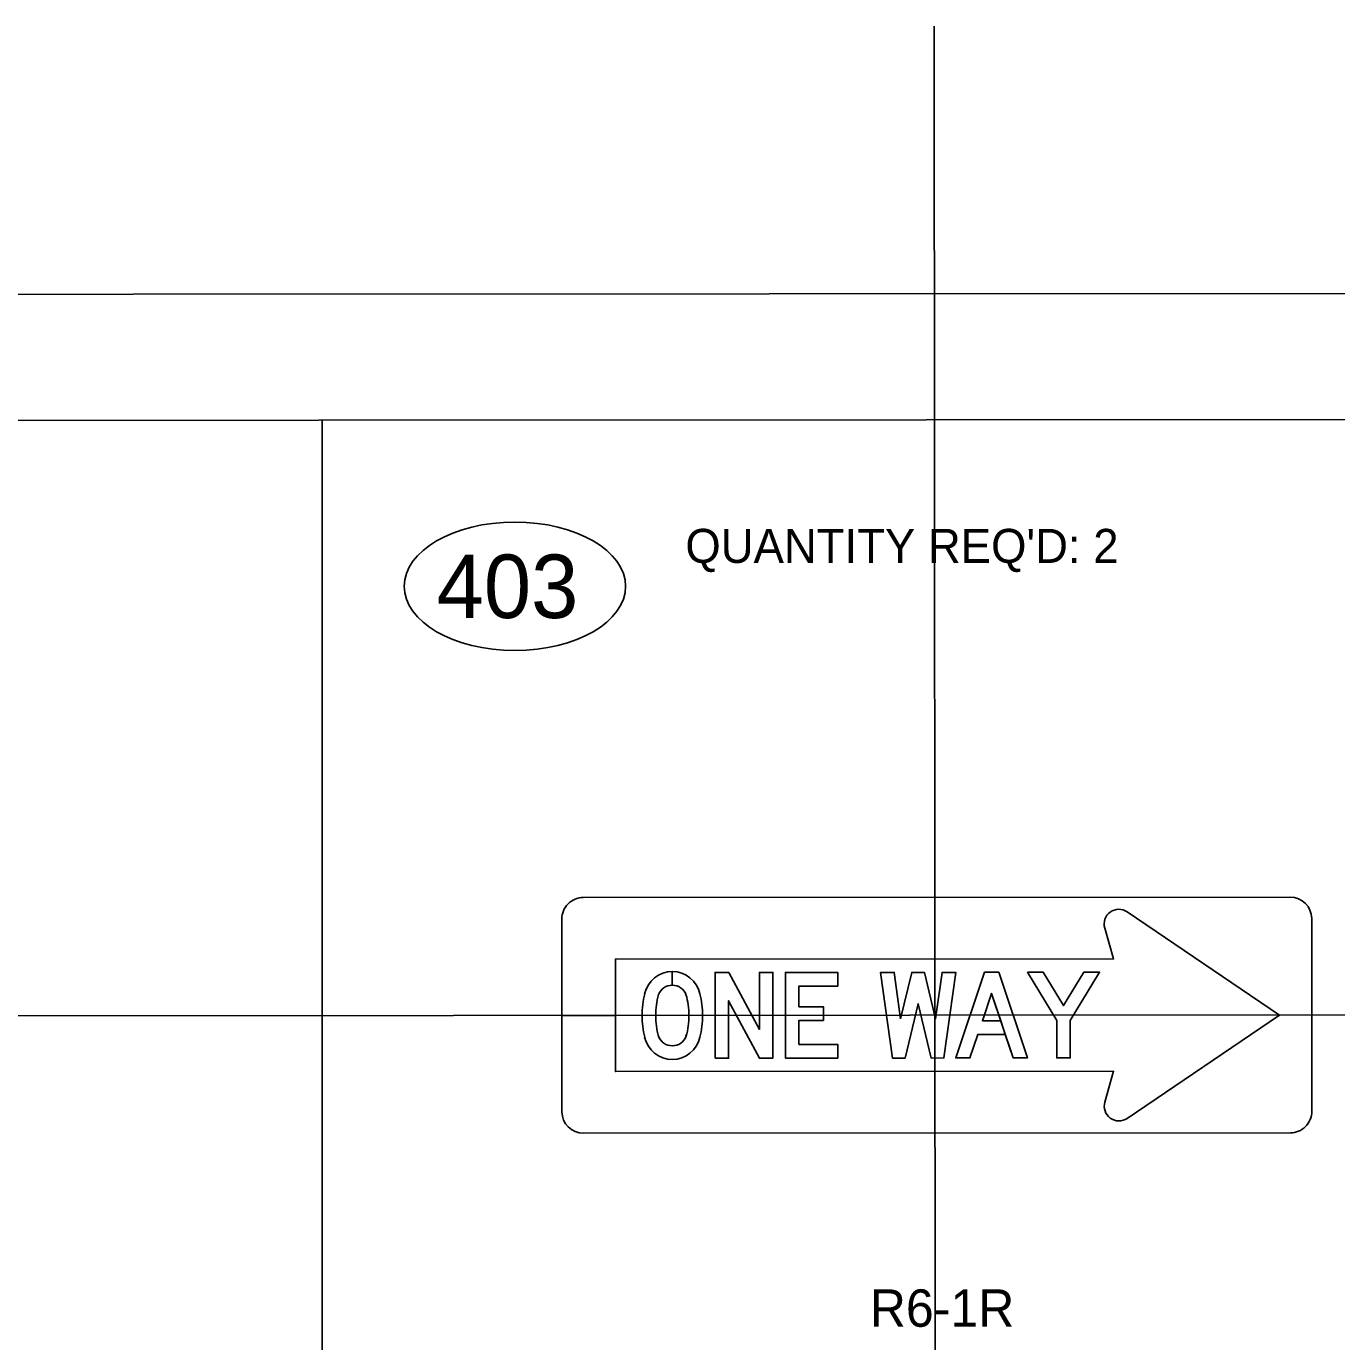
# Model space of a CAD drawing. Extents: x 1977705 to 1981198, y 827296 to 829291.
# Drawn here: x 1979879 to 1980110.2, y 828551.2 to 828783.3 of the extents above; entities that cross this region are included whole.
import ezdxf

# ---------------------------------------------------------------- set-up
doc = ezdxf.new("R2010")
doc.units = 0
for name, color, linetype in [('Level 3', 7, 'Continuous'), ('Level 34', 7, 'Continuous'), ('Level 43', 7, 'Continuous'), ('Level 7', 7, 'Continuous')]:
    doc.layers.add(name, color=color, linetype=linetype)

msp = doc.modelspace()

# ---------------------------------------------------------------- linework, layer by layer
at = {"layer": 'Level 3'}
msp.add_lwpolyline([(1981020.16, 828736.58), (1979336.66, 828735.68), (1979337.25, 827640.68), (1981020.75, 827641.58)], close=True, dxfattribs=at)
at = {"layer": 'Level 34'}
for p, q in [((1980039.8, 827664.08), (1980039.2, 828783.26)), ((1980814.89, 828609.21), (1979481.21, 828608.49))]:
    msp.add_line(p, q, dxfattribs=at)
at = {"layer": 'Level 43'}
for p, q in [((1979977.26, 828629.55), (1980102, 828629.61)), ((1980105.78, 828625.84), (1980105.8, 828591.82)), ((1979992.98, 828614.08), (1979992.97, 828616.51)), ((1979992.97, 828616.51), (1979992.98, 828614.08)), ((1979992.98, 828614.08), (1979992.97, 828616.51)), ((1979992.97, 828616.51), (1979992.98, 828614.08)), ((1979992.98, 828614.08), (1979992.98, 828614.08)), ((1979992.98, 828614.08), (1979992.98, 828614.08)), ((1980102.02, 828588.03), (1979977.28, 828587.97))]:
    msp.add_line(p, q, dxfattribs=at)
for points in [[(1980069.27, 828624.16), (1980070.82, 828618.73), (1979982.93, 828618.68), (1979982.94, 828608.76), (1979973.49, 828608.76), (1979973.48, 828625.77)], [(1980073.24, 828590.59), (1980100.12, 828608.82), (1980073.22, 828627.02)], [(1979973.5, 828591.75), (1979973.49, 828608.76), (1979982.94, 828608.76), (1979982.95, 828598.84), (1980070.83, 828598.89), (1980069.28, 828593.46)]]:
    msp.add_lwpolyline(points, dxfattribs=at)
for points in [[(1980000.52, 828601.21), (1980000.51, 828616.33), (1980002.93, 828616.33), (1980008.34, 828606.27), (1980008.34, 828616.33), (1980010.72, 828616.34), (1980010.73, 828601.22), (1980008.35, 828601.21), (1980002.9, 828611.33), (1980002.91, 828601.21)], [(1980000.52, 828601.21), (1980000.51, 828616.33), (1980002.93, 828616.33), (1980008.34, 828606.27), (1980008.34, 828616.33), (1980010.72, 828616.34), (1980010.73, 828601.22), (1980008.35, 828601.21), (1980002.9, 828611.33), (1980002.91, 828601.21)], [(1980000.52, 828601.21), (1980000.51, 828616.33), (1980002.93, 828616.33), (1980008.34, 828606.27), (1980008.34, 828616.33), (1980010.72, 828616.34), (1980010.73, 828601.22), (1980008.35, 828601.21), (1980002.9, 828611.33), (1980002.91, 828601.21)], [(1980022.16, 828613.92), (1980015.31, 828613.92), (1980015.31, 828610.29), (1980019.64, 828610.29), (1980019.64, 828607.87), (1980015.31, 828607.87), (1980015.31, 828603.64), (1980022.16, 828603.64), (1980022.16, 828601.22), (1980012.93, 828601.22), (1980012.92, 828616.34), (1980022.16, 828616.34)], [(1980022.16, 828613.92), (1980015.31, 828613.92), (1980015.31, 828610.29), (1980019.64, 828610.29), (1980019.64, 828607.87), (1980015.31, 828607.87), (1980015.31, 828603.64), (1980022.16, 828603.64), (1980022.16, 828601.22), (1980012.93, 828601.22), (1980012.92, 828616.34), (1980022.16, 828616.34)], [(1980022.16, 828613.92), (1980015.31, 828613.92), (1980015.31, 828610.29), (1980019.64, 828610.29), (1980019.64, 828607.87), (1980015.31, 828607.87), (1980015.31, 828603.64), (1980022.16, 828603.64), (1980022.16, 828601.22), (1980012.93, 828601.22), (1980012.92, 828616.34), (1980022.16, 828616.34)], [(1980033.25, 828608.17), (1980035.22, 828616.35), (1980037.46, 828616.35), (1980039.44, 828608.17), (1980040.56, 828616.35), (1980042.97, 828616.35), (1980040.89, 828601.24), (1980038.66, 828601.23), (1980036.34, 828610.82), (1980034.03, 828601.23), (1980031.81, 828601.23), (1980029.71, 828616.35), (1980032.12, 828616.35)], [(1980033.25, 828608.17), (1980035.22, 828616.35), (1980037.46, 828616.35), (1980039.44, 828608.17), (1980040.56, 828616.35), (1980042.97, 828616.35), (1980040.89, 828601.24), (1980038.66, 828601.23), (1980036.34, 828610.82), (1980034.03, 828601.23), (1980031.81, 828601.23), (1980029.71, 828616.35), (1980032.12, 828616.35)], [(1980033.25, 828608.17), (1980035.22, 828616.35), (1980037.46, 828616.35), (1980039.44, 828608.17), (1980040.56, 828616.35), (1980042.97, 828616.35), (1980040.89, 828601.24), (1980038.66, 828601.23), (1980036.34, 828610.82), (1980034.03, 828601.23), (1980031.81, 828601.23), (1980029.71, 828616.35), (1980032.12, 828616.35)], [(1980046.88, 828605.39), (1980045.49, 828601.24), (1980042.97, 828601.24), (1980048.03, 828616.36), (1980050.56, 828616.36), (1980055.63, 828601.24), (1980053.12, 828601.24), (1980051.72, 828605.4)], [(1980042.97, 828601.24), (1980048.03, 828616.36), (1980050.56, 828616.36), (1980055.63, 828601.24), (1980053.12, 828601.24), (1980049.3, 828612.62), (1980047.69, 828607.81), (1980050.91, 828607.81), (1980051.72, 828605.4), (1980046.88, 828605.39), (1980045.49, 828601.24)], [(1980042.97, 828601.24), (1980048.03, 828616.36), (1980050.56, 828616.36), (1980055.63, 828601.24), (1980053.12, 828601.24), (1980049.3, 828612.62), (1980047.69, 828607.81), (1980050.91, 828607.81), (1980051.72, 828605.4), (1980046.88, 828605.39), (1980045.49, 828601.24)], [(1980055.63, 828616.36), (1980060.81, 828607.86), (1980060.81, 828601.25), (1980063.19, 828601.25), (1980063.19, 828607.86), (1980068.36, 828616.37), (1980065.56, 828616.36), (1980062, 828610.5), (1980058.43, 828616.36)], [(1980055.63, 828616.36), (1980060.81, 828607.86), (1980060.81, 828601.25), (1980063.19, 828601.25), (1980063.19, 828607.86), (1980068.36, 828616.37), (1980065.56, 828616.36), (1980062, 828610.5), (1980058.43, 828616.36)], [(1980055.63, 828616.36), (1980060.81, 828607.86), (1980060.81, 828601.25), (1980063.19, 828601.25), (1980063.19, 828607.86), (1980068.36, 828616.37), (1980065.56, 828616.36), (1980062, 828610.5), (1980058.43, 828616.36)], [(1980047.69, 828607.81), (1980050.91, 828607.81), (1980049.3, 828612.62)]]:
    msp.add_lwpolyline(points, close=True, dxfattribs=at)
for centre, radius, start, end in [((1979977.26, 828625.77), 3.78, 90.0299, 180.0308), ((1980071.76, 828624.87), 2.6, 55.9136, 195.9857), ((1980102, 828625.83), 3.78, 0.0308, 90.0299), ((1980071.78, 828592.74), 2.6, 164.076, 304.148), ((1979977.28, 828591.75), 3.78, 180.0308, 270.0299), ((1980102.02, 828591.81), 3.78, 270.0299, 0.0308)]:
    msp.add_arc(centre, radius, start, end, dxfattribs=at)
for centre, major_axis, start_param, end_param in [((1979993.01, 828611.4), (0, 5.12), 0.007008, 1.34227), ((1979993.01, 828611.4), (0, 5.12), 0.007008, 1.34227), ((1979993.01, 828611.4), (0, 5.12), 0.007008, 1.34227), ((1979992.94, 828611.4), (0, 5.12), 4.940915, 6.276178), ((1979992.94, 828611.4), (0, 5.12), 4.940915, 6.27603), ((1979992.94, 828611.4), (0, 5.12), 4.940915, 6.27603), ((1979992.9, 828611.55), (0, 2.53), 6.252339, 7.504367), ((1979992.9, 828611.55), (0, 2.53), 6.252339, 7.504367), ((1979992.9, 828611.55), (0, 2.53), 6.252339, 7.504367), ((1979993.05, 828611.55), (0, 2.53), 5.062003, 6.314032), ((1979993.05, 828611.55), (0, 2.53), 5.062003, 6.313732), ((1979993.05, 828611.55), (0, 2.53), 5.062003, 6.313732), ((1980002.94, 828608.82), (-0.01, 15.52), 1.327472, 1.575821), ((1980002.94, 828608.82), (-0.01, 15.52), 1.327472, 1.575821), ((1980002.94, 828608.82), (-0.01, 15.52), 1.327472, 1.575821), ((1980001.26, 828609.02), (-0.01, 11.38), 1.267043, 1.594924), ((1980001.26, 828609.02), (-0.01, 11.38), 1.267042, 1.594924), ((1980001.26, 828609.02), (-0.01, 11.38), 1.267042, 1.594924), ((1979984.69, 828609.01), (-0.01, 11.38), 4.688261, 5.016143), ((1979984.69, 828609.01), (-0.01, 11.38), 4.688261, 5.016143), ((1979984.69, 828609.01), (-0.01, 11.38), 4.688261, 5.016143), ((1979983.02, 828608.81), (-0.01, 15.52), 4.707364, 4.955713), ((1979983.02, 828608.81), (-0.01, 15.52), 4.707364, 4.955713), ((1979983.02, 828608.81), (-0.01, 15.52), 4.707364, 4.955713), ((1980002.94, 828608.67), (-0.01, 15.52), 1.565772, 1.814121), ((1980002.94, 828608.67), (-0.01, 15.52), 1.565772, 1.814121), ((1980002.94, 828608.67), (-0.01, 15.52), 1.565772, 1.814121), ((1980001.26, 828608.47), (-0.01, 11.38), 1.546668, 1.87455), ((1980001.26, 828608.47), (-0.01, 11.38), 1.546668, 1.87455), ((1980001.26, 828608.47), (-0.01, 11.38), 1.546668, 1.87455), ((1979984.69, 828608.46), (-0.01, 11.38), 4.408635, 4.736517), ((1979984.69, 828608.46), (-0.01, 11.38), 4.408635, 4.736517), ((1979984.69, 828608.46), (-0.01, 11.38), 4.408635, 4.736517), ((1979983.02, 828608.66), (-0.01, 15.52), 4.469065, 4.717414), ((1979983.02, 828608.66), (-0.01, 15.52), 4.469065, 4.717414), ((1979983.02, 828608.66), (-0.01, 15.52), 4.469065, 4.717414), ((1979993.01, 828606.08), (0, 5.12), 1.799323, 3.134585), ((1979993.01, 828606.08), (0, 5.12), 1.799323, 3.134585), ((1979993.01, 828606.08), (0, 5.12), 1.799323, 3.134585), ((1979992.9, 828605.93), (0, 2.53), 1.920411, 3.172439), ((1979992.9, 828605.93), (0, 2.53), 1.920411, 3.172439), ((1979992.9, 828605.93), (0, 2.53), 1.920411, 3.172439), ((1979993.06, 828605.93), (0, 2.53), 3.110746, 4.362774), ((1979993.06, 828605.93), (0, 2.53), 3.110746, 4.362775), ((1979993.06, 828605.93), (0, 2.53), 3.110746, 4.362775), ((1979992.94, 828606.08), (0, 5.12), 3.1486, 4.483863), ((1979992.94, 828606.08), (0, 5.12), 3.1486, 4.483863), ((1979992.94, 828606.08), (0, 5.12), 3.1486, 4.483863)]:
    msp.add_ellipse(centre, major_axis=major_axis, ratio=0.985, start_param=start_param, end_param=end_param, dxfattribs=at)
at = {"layer": 'Level 7'}
msp.add_lwpolyline([(1981001.8, 828714.37), (1979502.12, 828713.56), (1979502.69, 827663.79), (1981002.36, 827664.6)], close=True, dxfattribs=at)
msp.add_lwpolyline([(1979931.19, 828713.79), (1979931.19, 827664.02)], dxfattribs=at)
msp.add_ellipse((1979965.2, 828684.46), major_axis=(-19.54, 0), ratio=0.580127, dxfattribs=at)

# ---------------------------------------------------------------- texts
for s, height, p in [("QUANTITY REQ'D: 2", 6, (1979995.28, 828688.59)), ('R6-1R', 6.6, (1980027.82, 828553.82))]:
    msp.add_text(s, height=height, dxfattribs=at).set_placement(p)
msp.add_text('403', height=11.202, rotation=359.9962, dxfattribs=at).set_placement((1979951.4, 828678.86))

doc.saveas('drawing.dxf')
